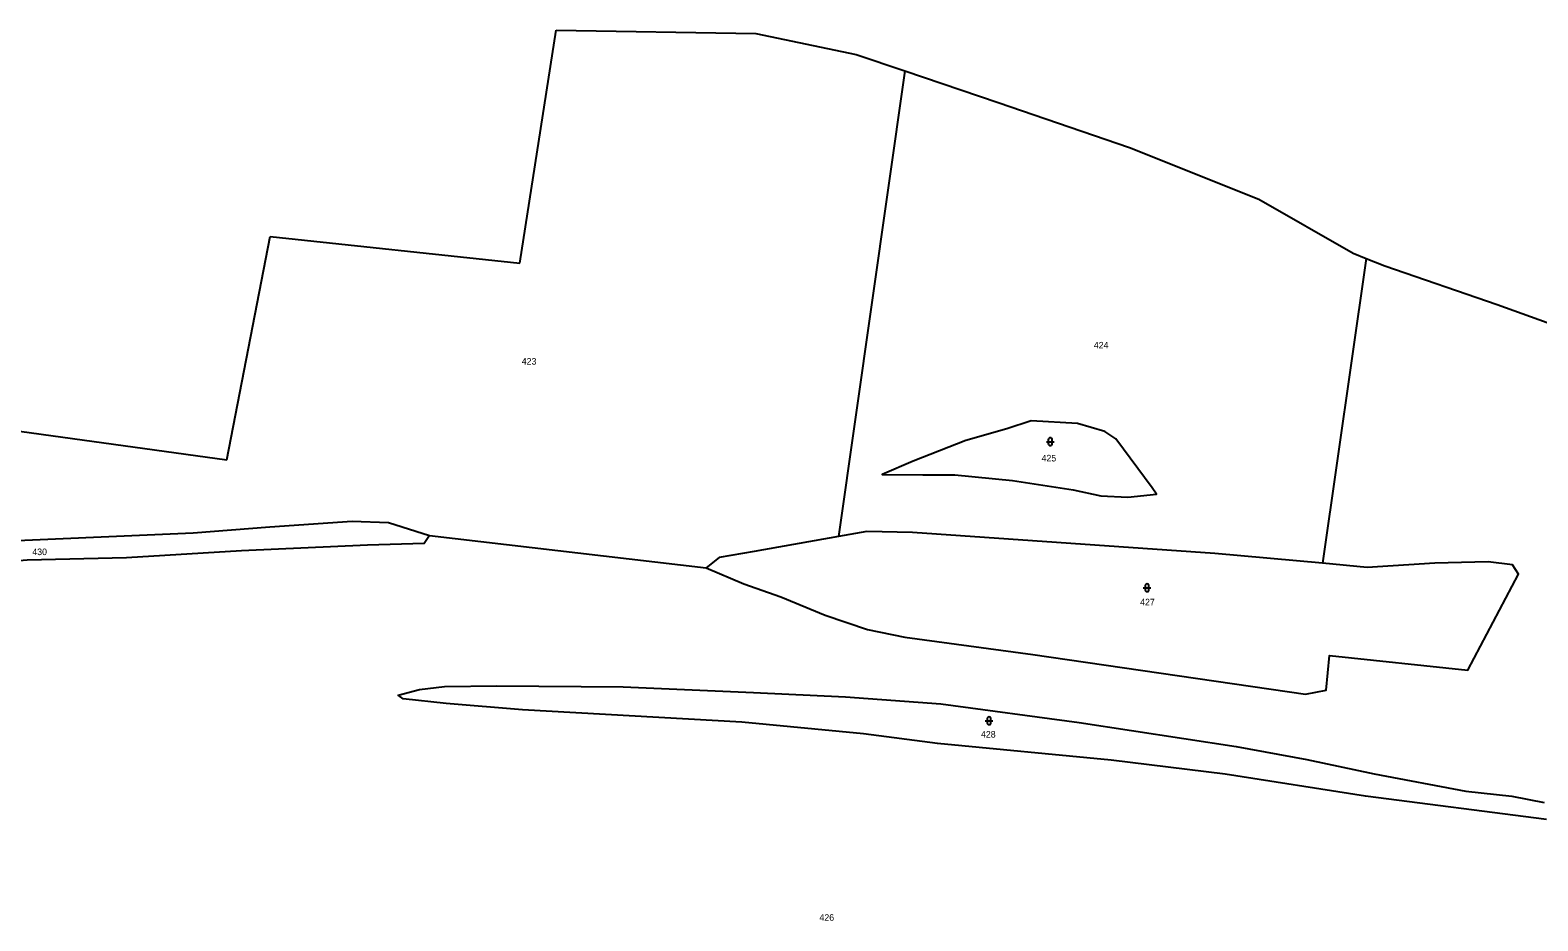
# Model space of a CAD drawing. Extents: x -769392 to -767038, y -1018329 to -1015269.
# Drawn here: x -768677.2 to -768286.9, y -1015765.3 to -1015534.9 of the extents above; entities that cross this region are included whole.
import ezdxf

# ---------------------------------------------------------------- set-up
doc = ezdxf.new("R2010")
doc.units = 0
doc.header["$LTSCALE"] = 0.68
doc.layers.add('1', color=7, linetype='Continuous', lineweight=25)
doc.layers.add('3', color=7, linetype='Continuous', lineweight=25)
doc.layers.add('2', color=7, linetype='Continuous')

msp = doc.modelspace()

# ---------------------------------------------------------------- linework, layer by layer
at = {"layer": '1'}
for p, q in [((-768550.41, -1015595.18), (-768541.05, -1015534.86)), ((-768541.05, -1015534.86), (-768489.39, -1015535.69)), ((-768489.39, -1015535.69), (-768463.42, -1015541.13)), ((-768463.42, -1015541.13), (-768450.79, -1015545.4)), ((-768450.79, -1015545.4), (-768468, -1015665.9)), ((-768450.79, -1015545.4), (-768426.6, -1015553.59)), ((-768426.6, -1015553.59), (-768392.64, -1015565.24)), ((-768392.64, -1015565.24), (-768359.17, -1015578.55)), ((-768359.17, -1015578.55), (-768334.78, -1015592.58)), ((-768626.24, -1015646.06), (-768615.08, -1015588.29)), ((-768615.08, -1015588.29), (-768550.41, -1015595.18)), ((-768334.78, -1015592.58), (-768331.38, -1015593.92)), ((-768331.38, -1015593.92), (-768342.65, -1015672.81)), ((-768331.38, -1015593.92), (-768326.57, -1015595.83)), ((-768326.57, -1015595.83), (-768297.46, -1015605.86)), ((-768297.46, -1015605.86), (-768268.23, -1015616.42)), ((-768684.96, -1015637.97), (-768626.24, -1015646.06)), ((-768573.84, -1015665.6), (-768502.23, -1015674))]:
    msp.add_line(p, q, dxfattribs=at)
msp.add_lwpolyline([(-768393.05, -1015655.73), (-768385.69, -1015654.91), (-768386.8, -1015653.32), (-768396.19, -1015640.59), (-768399.06, -1015638.73), (-768406.1, -1015636.68), (-768418.11, -1015635.93), (-768424.41, -1015638.03), (-768435.03, -1015641.01), (-768448.6, -1015646.4), (-768456.64, -1015649.85), (-768446.15, -1015649.92), (-768437.86, -1015649.94), (-768422.95, -1015651.36), (-768407.23, -1015653.77), (-768400.09, -1015655.34)], close=True, dxfattribs=at)
for points in [[(-768763.9, -1015674.89), (-768755.4, -1015673.86), (-768736.36, -1015669.92), (-768727.3, -1015668.71), (-768714.2, -1015667.85), (-768692.55, -1015667.47), (-768634.99, -1015664.91), (-768615.15, -1015663.36), (-768593.86, -1015661.93), (-768584.44, -1015662.23), (-768573.84, -1015665.6)], [(-768573.84, -1015665.6), (-768575.17, -1015667.68), (-768589.85, -1015668.08), (-768622.45, -1015669.56), (-768652.26, -1015671.4), (-768677.97, -1015671.97), (-768705.47, -1015674.31), (-768734.39, -1015678.16), (-768760.74, -1015682.48)], [(-768468, -1015665.9), (-768489.76, -1015669.77), (-768498.89, -1015671.33), (-768502.23, -1015674)], [(-768342.65, -1015672.81), (-768370.59, -1015670.28), (-768448.8, -1015664.86), (-768460.61, -1015664.58), (-768468, -1015665.9)], [(-768502.23, -1015674), (-768492.45, -1015678.14), (-768482.91, -1015681.47), (-768471.41, -1015686.24), (-768460.46, -1015689.93), (-768450.76, -1015691.91), (-768417.7, -1015696.41), (-768347.1, -1015706.71), (-768341.77, -1015705.66), (-768340.91, -1015696.66), (-768305.06, -1015700.46), (-768291.97, -1015675.66), (-768293.47, -1015673.25), (-768299.81, -1015672.44), (-768313.63, -1015672.75), (-768331.12, -1015673.86), (-768342.65, -1015672.81)], [(-768284.71, -1015739.14), (-768331.53, -1015733.07), (-768367.89, -1015727.4), (-768397.41, -1015723.78), (-768442.35, -1015719.47), (-768461.53, -1015716.93), (-768492.96, -1015713.89), (-768549.71, -1015710.7), (-768569.48, -1015709.1), (-768580.63, -1015707.88), (-768581.97, -1015706.92), (-768576.39, -1015705.48), (-768569.97, -1015704.72), (-768556.41, -1015704.54), (-768523.66, -1015704.81), (-768489.96, -1015706.27), (-768466.18, -1015707.38), (-768441.48, -1015709.14), (-768405.67, -1015714.03), (-768365.05, -1015720.24), (-768346.75, -1015723.54), (-768329.34, -1015727.25), (-768305.55, -1015731.78), (-768293.69, -1015733.05), (-768285.3, -1015734.67)]]:
    msp.add_lwpolyline(points, dxfattribs=at)
at = {"layer": '3'}
for p, q in [((-768414.151, -1015641.341), (-768412.149, -1015641.341)), ((-768413.651, -1015640.841), (-768413.651, -1015641.842)), ((-768412.649, -1015641.842), (-768412.649, -1015640.841)), ((-768388.601, -1015678.641), (-768388.601, -1015679.642)), ((-768387.599, -1015679.642), (-768387.599, -1015678.641)), ((-768389.101, -1015679.141), (-768387.099, -1015679.141)), ((-768429.991, -1015713.561), (-768427.989, -1015713.561)), ((-768429.491, -1015713.061), (-768429.491, -1015714.062)), ((-768428.489, -1015714.062), (-768428.489, -1015713.061))]:
    msp.add_line(p, q, dxfattribs=at)
for centre, start, end in [((-768413.15, -1015640.8409), 0, 180), ((-768413.15, -1015641.8409), 180, 359.98789), ((-768388.1, -1015678.6409), 0, 180), ((-768388.1, -1015679.6409), 180, 359.98789), ((-768428.99, -1015713.0609), 0, 180), ((-768428.99, -1015714.0609), 180, 359.98789)]:
    msp.add_arc(centre, 0.5, start, end, dxfattribs=at)

# ---------------------------------------------------------------- texts
at = {"layer": '2'}
for s, p in [('424', (-768401.88, -1015617.225)), ('423', (-768549.94, -1015621.395)), ('425', (-768415.4, -1015646.455)), ('430', (-768676.63, -1015670.695)), ('427', (-768389.89, -1015683.705)), ('428', (-768431.08, -1015717.915)), ('426', (-768472.89, -1015765.305))]:
    msp.add_text(s, height=1.7, dxfattribs=at).set_placement(p)

doc.saveas('drawing.dxf')
